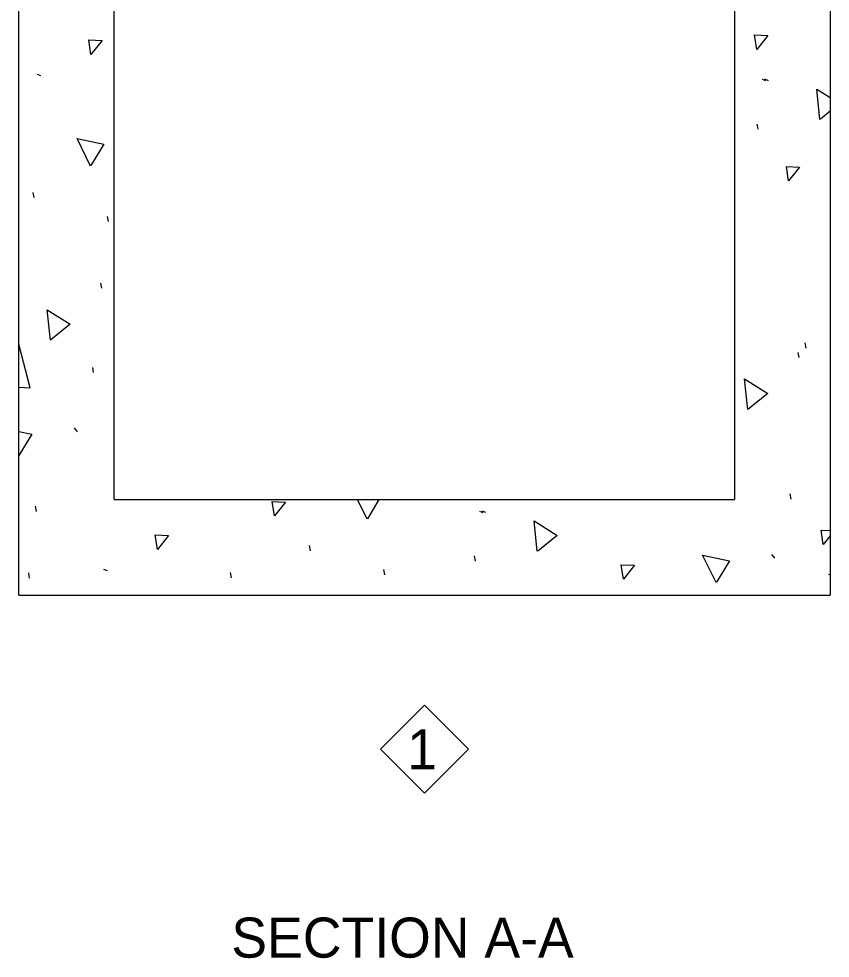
# Model space of a CAD drawing. Extents: x 49991.4 to 50029.7, y 49987.6 to 50011.4.
# Drawn here: x 50019.517 to 50021.137, y 49990.286 to 49992.163 of the extents above; entities that cross this region are included whole.
import ezdxf

# ---------------------------------------------------------------- set-up
doc = ezdxf.new("R2010")
doc.units = 0
for name, color, linetype in [('Level 1', 7, 'Continuous'), ('Level 2', 7, 'Continuous'), ('Level 20', 7, 'Continuous'), ('Level 9', 7, 'Continuous')]:
    doc.layers.add(name, color=color, linetype=linetype)

msp = doc.modelspace()

# ---------------------------------------------------------------- linework, layer by layer
at = {"layer": 'Level 1'}
for p, q in [((50019.5175, 49991.0114), (50019.5175, 49993.1685)), ((50021.1375, 49993.1696), (50021.1375, 49991.0114)), ((50019.7082, 49991.2021), (50019.7082, 49992.9949)), ((50020.9467, 49992.9949), (50020.9467, 49991.2021)), ((50019.7082, 49991.2021), (50020.9467, 49991.2021)), ((50019.5175, 49991.0114), (50021.1375, 49991.0114))]:
    msp.add_line(p, q, dxfattribs=at)
at = {"layer": 'Level 20'}
msp.add_lwpolyline([(50020.3275, 49990.7914), (50020.4152, 49990.7036), (50020.3275, 49990.6158), (50020.2397, 49990.7036)], close=True, dxfattribs=at)
at = {"layer": 'Level 9'}
for p, q in [((50019.554, 49992.0521), (50019.5611, 49992.0492)), ((50021.0013, 49992.042), (50021.0084, 49992.0391)), ((50021.0062, 49992.0423), (50021.0133, 49992.0394)), ((50020.9934, 49991.942), (50020.9916, 49991.9522)), ((50019.548, 49991.8055), (50019.5462, 49991.8157)), ((50019.6966, 49991.7575), (50019.6948, 49991.7678)), ((50019.683, 49991.6243), (50019.6812, 49991.6346)), ((50021.0892, 49991.5047), (50021.0874, 49991.515)), ((50021.0756, 49991.4861), (50021.0738, 49991.4963)), ((50019.6669, 49991.456), (50019.6651, 49991.4663)), ((50019.6277, 49991.3452), (50019.6339, 49991.3378)), ((50021.0595, 49991.2032), (50021.0577, 49991.2135)), ((50019.5527, 49991.1785), (50019.5509, 49991.1888)), ((50020.4371, 49991.1794), (50020.4442, 49991.1765)), ((50020.4419, 49991.1798), (50020.449, 49991.1769)), ((50020.0999, 49991.1001), (50020.0981, 49991.1103)), ((50020.4292, 49991.0794), (50020.4274, 49991.0897)), ((50021.0203, 49991.0924), (50021.0265, 49991.0851)), ((50019.5391, 49991.0453), (50019.5373, 49991.0556)), ((50019.6867, 49991.0632), (50019.6938, 49991.0603)), ((50019.9422, 49991.0461), (50019.9404, 49991.0563)), ((50020.2484, 49991.0521), (50020.2466, 49991.0624)), ((50021.134, 49991.053), (50021.1375, 49991.0516))]:
    msp.add_line(p, q, dxfattribs=at)
for points in [[(50020.9908, 49992.1012), (50020.9865, 49992.1303), (50021.0129, 49992.1289), (50020.9908, 49992.1012)], [(50019.6616, 49992.0915), (50019.6573, 49992.1205), (50019.6838, 49992.1192), (50019.6616, 49992.0915)], [(50021.117, 49991.9614), (50021.1105, 49992.0222), (50021.1375, 49992.0054)], [(50021.1375, 49991.9779), (50021.1178, 49991.962)], [(50019.6609, 49991.8684), (50019.6341, 49991.9232), (50019.6874, 49991.912), (50019.6616, 49991.8692)], [(50021.0542, 49991.8387), (50021.0499, 49991.8677), (50021.0763, 49991.8664), (50021.0542, 49991.8387)], [(50019.5805, 49991.5207), (50019.574, 49991.5815), (50019.6202, 49991.5527), (50019.5814, 49991.5213)], [(50019.5177, 49991.5125), (50019.5175, 49991.5142)], [(50019.5175, 49991.4268), (50019.5399, 49991.4257), (50019.5177, 49991.5125)], [(50020.9731, 49991.3824), (50020.9666, 49991.4432), (50021.0128, 49991.4144), (50020.974, 49991.383)], [(50019.5175, 49991.3385), (50019.5435, 49991.333), (50019.5177, 49991.2902)], [(50020.2128, 49991.163), (50020.1936, 49991.2021)], [(50020.2365, 49991.2021), (50020.2134, 49991.1639)], [(50020.0277, 49991.1695), (50020.0235, 49991.1986), (50020.0499, 49991.1973), (50020.0277, 49991.1695)], [(50020.5527, 49991.0989), (50020.5462, 49991.1596), (50020.5925, 49991.1308), (50020.5536, 49991.0995)], [(50019.7942, 49991.1025), (50019.79, 49991.1315), (50019.8164, 49991.1302), (50019.7942, 49991.1025)], [(50021.1234, 49991.1123), (50021.1191, 49991.1413), (50021.1375, 49991.1404)], [(50021.1375, 49991.1299), (50021.1234, 49991.1123)], [(50020.9097, 49991.0366), (50020.8828, 49991.0915), (50020.9361, 49991.0802), (50020.9103, 49991.0375)], [(50020.7246, 49991.0431), (50020.7204, 49991.0722), (50020.7468, 49991.0709), (50020.7246, 49991.0431)]]:
    msp.add_lwpolyline(points, dxfattribs=at)

# ---------------------------------------------------------------- texts
at = {"layer": 'Level 2'}
msp.add_text('SECTION A-A', height=0.08, dxfattribs=at).set_placement((50019.9418, 49990.2873))
at = {"layer": 'Level 20'}
msp.add_text('1', height=0.08, dxfattribs=at).set_placement((50020.2931, 49990.6636))

doc.saveas('drawing.dxf')
